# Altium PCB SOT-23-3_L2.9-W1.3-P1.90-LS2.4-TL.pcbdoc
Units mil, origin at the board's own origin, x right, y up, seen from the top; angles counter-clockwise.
Board outline 648.81 x 616.92 mil, 2 copper layers (Top Layer, Bottom Layer), stack 0 mil thick; 1 components, 0 nets, 3 pads, 0 vias.
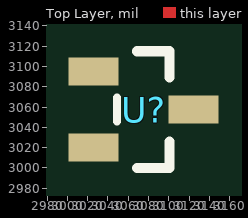
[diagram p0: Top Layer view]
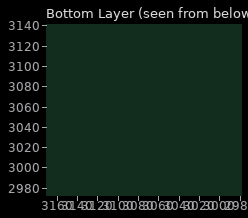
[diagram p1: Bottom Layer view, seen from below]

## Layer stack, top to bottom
Top Layer: signal copper (thickness not stored)
Bottom Layer: signal copper (thickness not stored)

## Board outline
3398.81,2750 2750,2750 2750,3366.92 3398.81,3366.92

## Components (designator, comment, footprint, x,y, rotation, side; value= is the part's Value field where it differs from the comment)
U? "" SOT-23-3_L2.9-W1.3-P1.90-LS2.4-TL 3075,3057.48 r0 top

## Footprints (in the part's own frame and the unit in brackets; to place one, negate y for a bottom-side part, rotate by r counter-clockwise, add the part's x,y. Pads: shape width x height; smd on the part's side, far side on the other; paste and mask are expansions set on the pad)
SOT-23-3_L2.9-W1.3-P1.90-LS2.4-TL [mm]
  rect 1.25x0.7 smd: 1(-1.25,0.95) 2(-1.25,-0.95) 3(1.25,0)
  silkscreen extent -0.66,-1.46 0.65,1.46

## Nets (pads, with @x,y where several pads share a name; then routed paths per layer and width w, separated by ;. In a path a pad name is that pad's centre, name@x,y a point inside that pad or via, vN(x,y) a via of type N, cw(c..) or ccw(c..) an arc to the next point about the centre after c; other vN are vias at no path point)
pads on no net: U?.1 U?.2 U?.3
